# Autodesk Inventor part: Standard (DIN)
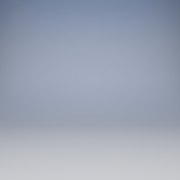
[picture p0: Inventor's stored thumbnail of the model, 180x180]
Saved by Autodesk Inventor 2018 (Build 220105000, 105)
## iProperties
Created: 2017-02
Part Number: Standard (DIN)
Material: Ogólny
Document SubType Name: Modeling
Density: 1 g/cm^3
Appearance: Domyślna
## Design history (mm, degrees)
